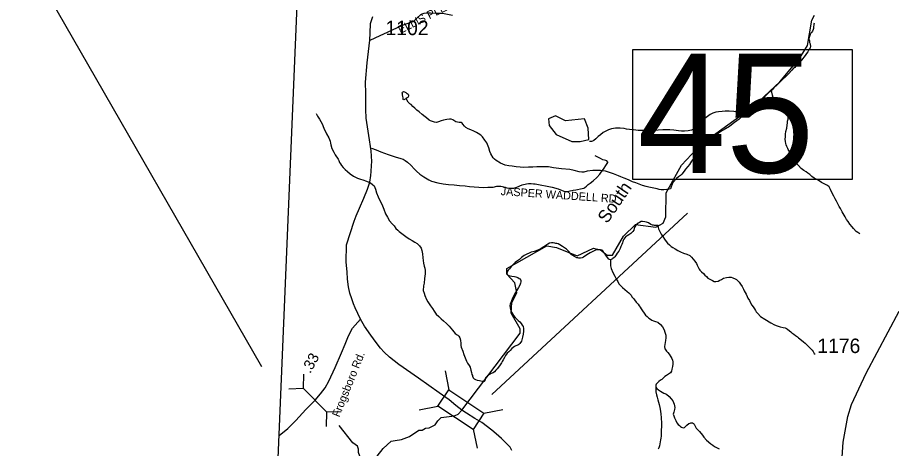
# Model space of a CAD drawing. Extents: x 1950930 to 2061844, y 904556 to 1017002.
# Drawn here: x 1953252 to 1963523, y 946514 to 951576 of the extents above; entities that cross this region are included whole.
import ezdxf

# ---------------------------------------------------------------- set-up
doc = ezdxf.new("R2010")
doc.units = 0
for name, color, linetype in [('Exist Boundary Political CountyLine', 7, 'Continuous'), ('Exist Hydrographic Creek Single Shore', 7, 'Continuous'), ('Exist Hydrographic Creek Single Shore Label', 7, 'Continuous'), ('Exist Hydrographic Misc Water Feature', 7, 'Continuous'), ('Exist Road Non-System Type 51', 7, 'Continuous'), ('Exist Road Non-System Type 51 Label', 7, 'Continuous'), ('Exist Road Primary Interstate Structure Ovrhead Sign Attributed CELL', 7, 'Continuous'), ('Exist Road Primary US Structure Standard Bridge CELL', 7, 'Continuous'), ('Exist Road Secondary Structure Pipe Number Label', 7, 'Continuous'), ('Exist Road Secondary Structure Standard Bridge CELL', 7, 'Continuous'), ('Exist Road Secondary Structure Standard Bridge Number Label', 7, 'Continuous'), ('Exist Road Secondary Type 41 Attributed', 7, 'Continuous'), ('Exist Road Secondary Type 51 Attributed', 7, 'Continuous'), ('Exist Road Secondary Type 51 Label', 7, 'Continuous'), ('Exist Road Secondary Type 51 Number Label', 7, 'Continuous')]:
    doc.layers.add(name, color=color, linetype=linetype)

msp = doc.modelspace()

# ---------------------------------------------------------------- linework, layer by layer
at = {"layer": 'Exist Boundary Political CountyLine'}
msp.add_lwpolyline([(1954667, 907078), (1956980, 962279), (1958720, 998184), (1959482, 1016167)], dxfattribs=at)
at = {"layer": 'Exist Hydrographic Creek Single Shore'}
for points in [[(1957969, 946730), (1958006, 946730), (1958048, 946752), (1958090, 946758), (1958159, 946790), (1958193, 946839), (1958230, 946879), (1958357, 946895), (1958397, 946900), (1958431, 946919), (1958473, 946966), (1959161, 947868), (1959161, 947920), (1959053, 948103), (1959062, 948227), (1959120, 948344), (1959095, 948460), (1959004, 948560), (1959004, 948629), (1959471, 948895), (1959588, 948876), (1959829, 948776), (1960021, 948867), (1960105, 948849), (1960180, 948785), (1960246, 948784), (1960372, 949008), (1960514, 949143), (1960755, 949115), (1960839, 949159), (1960872, 949234), (1960873, 949516), (1961057, 949840), (1961291, 950092), (1961908, 950538), (1962209, 950821), (1962451, 951105), (1962535, 951247), (1962585, 951545), (1962619, 951604)], [(1960779, 949133), (1960777, 949129), (1960781, 949111), (1960785, 949093), (1960795, 949071), (1960817, 949033), (1960835, 949005), (1960855, 948973), (1960875, 948943), (1960889, 948927), (1960915, 948905), (1960935, 948887), (1960953, 948873), (1960979, 948859), (1961013, 948841), (1961045, 948825), (1961079, 948809), (1961119, 948795), (1961152, 948779), (1961174, 948759), (1961194, 948737), (1961212, 948715), (1961230, 948688), (1961238, 948666), (1961250, 948642), (1961262, 948620), (1961272, 948610), (1961290, 948590), (1961314, 948570), (1961330, 948548), (1961348, 948534), (1961366, 948514), (1961388, 948504), (1961418, 948486), (1961438, 948476), (1961450, 948474), (1961460, 948474), (1961484, 948480), (1961504, 948490), (1961526, 948500), (1961550, 948514), (1961582, 948524), (1961612, 948528), (1961638, 948526), (1961660, 948518), (1961684, 948506), (1961700, 948498), (1961714, 948486), (1961732, 948467), (1961750, 948443), (1961768, 948415), (1961782, 948385), (1961792, 948365), (1961804, 948345), (1961814, 948325), (1961828, 948299), (1961836, 948281), (1961853, 948253), (1961863, 948233), (1961883, 948197), (1961897, 948177), (1961911, 948155), (1961925, 948133), (1961933, 948119), (1961951, 948099), (1961985, 948065), (1962033, 948031), (1962103, 947989), (1962149, 947967), (1962179, 947953), (1962213, 947942), (1962249, 947936), (1962275, 947930), (1962289, 947924), (1962301, 947914), (1962325, 947896), (1962339, 947884), (1962353, 947872), (1962375, 947856), (1962395, 947842), (1962417, 947826), (1962431, 947814), (1962445, 947800), (1962487, 947768), (1962507, 947750), (1962531, 947728), (1962552, 947708), (1962571, 947690), (1962589, 947670), (1962602, 947652), (1962616, 947630), (1962626, 947622)], [(1960220, 948730), (1960220, 948724), (1960220, 948702), (1960222, 948660), (1960228, 948626), (1960250, 948580), (1960270, 948538), (1960292, 948500), (1960306, 948474), (1960320, 948448), (1960342, 948426), (1960362, 948404), (1960388, 948382), (1960417, 948358), (1960436, 948342), (1960462, 948314), (1960473, 948294), (1960491, 948276), (1960503, 948258), (1960523, 948234), (1960547, 948208), (1960559, 948190), (1960569, 948174), (1960581, 948154), (1960597, 948130), (1960615, 948104), (1960633, 948081), (1960653, 948064), (1960667, 948049), (1960679, 948039), (1960705, 948023), (1960725, 948015), (1960751, 948005), (1960775, 947997), (1960809, 947971), (1960831, 947941), (1960851, 947909), (1960861, 947881), (1960869, 947845), (1960871, 947813), (1960867, 947783), (1960862, 947759), (1960856, 947711), (1960858, 947685), (1960862, 947681), (1960880, 947657), (1960894, 947641), (1960910, 947621), (1960928, 947591), (1960940, 947571), (1960948, 947553), (1960954, 947531), (1960952, 947503), (1960950, 947477), (1960942, 947445), (1960936, 947423), (1960924, 947401), (1960902, 947385), (1960878, 947371), (1960860, 947359), (1960842, 947343), (1960822, 947325), (1960807, 947315), (1960790, 947301), (1960782, 947293), (1960764, 947277), (1960759, 947269), (1960755, 947259), (1960753, 947245), (1960753, 947233)], [(1960753, 947233), (1960753, 947217), (1960753, 947197), (1960753, 947181), (1960761, 947145), (1960769, 947115), (1960775, 947087), (1960785, 947059), (1960793, 947031), (1960801, 946995), (1960807, 946953), (1960811, 946917), (1960815, 946879), (1960817, 946859), (1960819, 946827), (1960819, 946803), (1960819, 946777), (1960816, 946727), (1960816, 946709), (1960816, 946687), (1960816, 946659), (1960814, 946637), (1960808, 946615), (1960806, 946591), (1960802, 946569), (1960798, 946545), (1960788, 946521), (1960782, 946507)], [(1957255, 946350), (1957267, 946376), (1957285, 946395), (1957274, 946425), (1957258, 946466), (1957260, 946505), (1957249, 946542), (1957193, 946579), (1957033, 946783)], [(1957255, 946350), (1957358, 946345), (1957410, 946360), (1957479, 946425), (1957550, 946513), (1957642, 946600), (1957689, 946607), (1957765, 946621), (1957858, 946655), (1957969, 946730)]]:
    msp.add_lwpolyline(points, dxfattribs=at)
at = {"layer": 'Exist Hydrographic Misc Water Feature'}
for points in [[(1962616, 951510), (1962612, 951498), (1962610, 951488), (1962608, 951466), (1962606, 951446), (1962602, 951434), (1962594, 951416), (1962586, 951402), (1962574, 951390), (1962568, 951378), (1962562, 951366), (1962554, 951342), (1962550, 951326), (1962553, 951312), (1962559, 951300), (1962561, 951284), (1962566, 951268), (1962566, 951256), (1962571, 951248), (1962571, 951236), (1962567, 951218), (1962557, 951202), (1962539, 951172), (1962525, 951154), (1962507, 951128), (1962465, 951076), (1962441, 951048), (1962413, 951019), (1962399, 951005), (1962385, 950989), (1962373, 950979), (1962351, 950957), (1962313, 950915), (1962287, 950887), (1962239, 950843), (1962215, 950821), (1962196, 950801), (1962178, 950785), (1962140, 950749), (1962122, 950727), (1962114, 950721)], [(1957818, 950625), (1957814, 950621), (1957798, 950611), (1957790, 950607), (1957786, 950611), (1957784, 950631), (1957782, 950649), (1957778, 950669), (1957776, 950683), (1957774, 950689), (1957776, 950699), (1957788, 950705), (1957798, 950701), (1957808, 950697), (1957816, 950693), (1957824, 950687), (1957830, 950685), (1957842, 950677), (1957846, 950663), (1957846, 950651), (1957844, 950645), (1957838, 950637), (1957830, 950631), (1957818, 950625)], [(1962114, 950721), (1962104, 950711), (1962082, 950693), (1962062, 950675), (1962024, 950637), (1961978, 950591), (1961924, 950547), (1961880, 950507), (1961848, 950482), (1961818, 950458), (1961794, 950438), (1961788, 950434)], [(1963149, 949035), (1963127, 949049), (1963109, 949061), (1963075, 949097), (1963059, 949119), (1963035, 949147), (1963012, 949181), (1962996, 949205), (1962980, 949233), (1962966, 949253), (1962944, 949293), (1962922, 949331), (1962906, 949357), (1962892, 949389), (1962876, 949419), (1962862, 949447), (1962846, 949477), (1962820, 949522), (1962806, 949554), (1962790, 949586), (1962770, 949604), (1962730, 949624), (1962700, 949638), (1962672, 949656), (1962646, 949672), (1962614, 949688), (1962587, 949710), (1962563, 949730), (1962539, 949748), (1962519, 949762), (1962493, 949780), (1962463, 949802), (1962431, 949836), (1962411, 949856), (1962395, 949876), (1962385, 949892), (1962371, 949914), (1962363, 949930), (1962357, 949944), (1962335, 949981), (1962309, 950025), (1962303, 950039), (1962293, 950061), (1962287, 950081), (1962281, 950097), (1962277, 950119), (1962275, 950145), (1962277, 950175), (1962279, 950189), (1962279, 950207), (1962283, 950235), (1962291, 950275), (1962298, 950311), (1962300, 950337), (1962302, 950359), (1962308, 950381), (1962310, 950403), (1962312, 950429), (1962308, 950445), (1962304, 950459), (1962300, 950469), (1962288, 950487), (1962268, 950501), (1962238, 950515), (1962220, 950525), (1962194, 950543), (1962176, 950559), (1962164, 950573), (1962156, 950587), (1962144, 950607), (1962138, 950621), (1962126, 950663), (1962118, 950697), (1962114, 950721)], [(1960924, 949565), (1960912, 949561), (1960884, 949555), (1960846, 949551), (1960816, 949553), (1960792, 949555), (1960768, 949562), (1960728, 949570), (1960670, 949582), (1960638, 949590), (1960598, 949604), (1960558, 949618), (1960520, 949632), (1960480, 949646), (1960434, 949668), (1960382, 949688), (1960342, 949706), (1960314, 949716), (1960254, 949739), (1960198, 949761), (1960162, 949771), (1960130, 949775), (1960104, 949777), (1960066, 949777), (1960014, 949777), (1959948, 949771), (1959906, 949761), (1959882, 949759), (1959854, 949763), (1959792, 949779), (1959742, 949789), (1959644, 949798), (1959550, 949812), (1959492, 949820), (1959426, 949822), (1959354, 949820), (1959308, 949818), (1959256, 949816), (1959200, 949815), (1959160, 949817), (1959114, 949823), (1959064, 949829), (1959024, 949835), (1958982, 949843), (1958954, 949853), (1958928, 949865), (1958878, 949897), (1958856, 949913), (1958840, 949929), (1958816, 949973), (1958802, 950001), (1958789, 950045), (1958767, 950103), (1958745, 950135), (1958717, 950176), (1958697, 950194), (1958665, 950214), (1958645, 950224), (1958615, 950240), (1958581, 950256), (1958549, 950268), (1958519, 950284), (1958503, 950298), (1958485, 950324), (1958479, 950334), (1958465, 950342), (1958443, 950344), (1958421, 950346), (1958403, 950350), (1958367, 950372), (1958349, 950380), (1958327, 950382), (1958299, 950378), (1958257, 950369), (1958229, 950361), (1958199, 950349), (1958175, 950343), (1958151, 950345), (1958129, 950353), (1958107, 950363), (1958091, 950369), (1958057, 950397), (1958041, 950411), (1958009, 950437), (1957973, 950467), (1957943, 950489), (1957923, 950509), (1957899, 950531), (1957877, 950553), (1957864, 950563), (1957844, 950583), (1957826, 950609), (1957818, 950625)], [(1956763, 950449), (1956779, 950417), (1956801, 950383), (1956831, 950327), (1956853, 950275), (1956885, 950209), (1956911, 950161), (1956925, 950125), (1956931, 950099), (1956934, 950081), (1956944, 950039), (1956968, 949995), (1956986, 949963), (1957020, 949911), (1957030, 949895), (1957036, 949873), (1957048, 949857), (1957060, 949839), (1957080, 949813), (1957104, 949789), (1957128, 949769), (1957162, 949739), (1957200, 949712), (1957248, 949690), (1957284, 949678), (1957312, 949670), (1957352, 949652), (1957382, 949642), (1957400, 949634), (1957424, 949616), (1957444, 949598), (1957460, 949560), (1957469, 949518), (1957491, 949468), (1957511, 949428), (1957533, 949384), (1957555, 949324), (1957577, 949270), (1957599, 949230), (1957625, 949189), (1957653, 949153), (1957677, 949127), (1957699, 949099), (1957721, 949077), (1957737, 949061), (1957767, 949037), (1957817, 949003), (1957856, 948977), (1957890, 948957), (1957920, 948939), (1957950, 948923), (1957978, 948895), (1957994, 948867), (1958002, 948839), (1958012, 948801), (1958016, 948753), (1958024, 948691), (1958032, 948657), (1958040, 948633), (1958044, 948605), (1958044, 948567), (1958040, 948539), (1958036, 948509), (1958031, 948457), (1958025, 948423), (1958021, 948371), (1958029, 948339), (1958039, 948311), (1958057, 948263), (1958073, 948236), (1958107, 948188), (1958127, 948160), (1958147, 948126), (1958173, 948090), (1958203, 948064), (1958231, 948038), (1958259, 948014), (1958295, 947982), (1958324, 947952), (1958346, 947926), (1958364, 947902), (1958396, 947866), (1958418, 947850), (1958428, 947844), (1958440, 947834), (1958452, 947814), (1958456, 947786), (1958460, 947748), (1958462, 947724), (1958466, 947704), (1958484, 947656), (1958496, 947616), (1958512, 947580), (1958530, 947541), (1958542, 947517), (1958558, 947487), (1958570, 947470), (1958580, 947435), (1958589, 947407), (1958593, 947383)], [(1961788, 950434), (1961756, 950448), (1961708, 950464), (1961672, 950470), (1961614, 950476), (1961568, 950474), (1961532, 950472), (1961490, 950466), (1961458, 950462), (1961424, 950452), (1961392, 950436), (1961362, 950414), (1961308, 950373), (1961280, 950345), (1961258, 950319), (1961233, 950295), (1961205, 950269), (1961173, 950253), (1961133, 950245), (1961091, 950239), (1961055, 950241), (1961021, 950245), (1960993, 950247), (1960965, 950251), (1960919, 950255), (1960871, 950257), (1960837, 950255), (1960779, 950252), (1960717, 950250), (1960683, 950250), (1960643, 950250), (1960607, 950250), (1960581, 950250), (1960547, 950250), (1960491, 950256), (1960445, 950262), (1960409, 950266), (1960381, 950272), (1960335, 950276), (1960281, 950275), (1960233, 950267), (1960199, 950255), (1960157, 950237), (1960135, 950225), (1960103, 950199), (1960077, 950177), (1960049, 950151), (1960025, 950133), (1960011, 950125), (1959997, 950121), (1959975, 950121)], [(1961788, 950434), (1961764, 950412), (1961732, 950382), (1961678, 950342), (1961643, 950314), (1961618, 950296), (1961573, 950268), (1961537, 950248), (1961491, 950218), (1961465, 950198), (1961429, 950168), (1961411, 950154), (1961385, 950130), (1961363, 950108), (1961351, 950092), (1961333, 950070), (1961313, 950050), (1961285, 950026), (1961261, 950001), (1961215, 949943), (1961187, 949909), (1961173, 949887), (1961148, 949851), (1961130, 949825), (1961104, 949793), (1961088, 949771), (1961060, 949737), (1961042, 949719), (1961018, 949703), (1960996, 949685), (1960958, 949641), (1960944, 949617), (1960932, 949587), (1960924, 949565)], [(1959865, 950118), (1959966, 950142), (1959957, 950277), (1959916, 950386), (1959691, 950361), (1959574, 950419), (1959491, 950385), (1959499, 950309), (1959582, 950202), (1959765, 950120), (1959865, 950118)], [(1960779, 949133), (1960761, 949131), (1960739, 949131), (1960725, 949136), (1960715, 949137), (1960695, 949145), (1960667, 949164), (1960643, 949172), (1960625, 949176), (1960597, 949180), (1960581, 949178), (1960561, 949170), (1960545, 949160), (1960519, 949138), (1960505, 949118), (1960499, 949098), (1960493, 949078), (1960483, 949064), (1960473, 949050), (1960461, 949040), (1960449, 949030), (1960437, 949022), (1960417, 949012), (1960401, 949002), (1960389, 948988), (1960379, 948974), (1960371, 948958), (1960367, 948944), (1960363, 948928), (1960355, 948908), (1960344, 948888), (1960335, 948862), (1960319, 948832), (1960300, 948808), (1960286, 948788), (1960272, 948766), (1960264, 948758), (1960250, 948746), (1960246, 948742), (1960230, 948732), (1960226, 948730), (1960220, 948730)], [(1960220, 948730), (1960210, 948732), (1960206, 948734), (1960198, 948742), (1960188, 948755), (1960172, 948773), (1960158, 948795), (1960148, 948807), (1960140, 948823), (1960132, 948835), (1960121, 948843), (1960105, 948847), (1960099, 948847), (1960075, 948849), (1960051, 948847), (1960020, 948831), (1959982, 948813), (1959944, 948789), (1959904, 948761), (1959888, 948753), (1959868, 948751), (1959850, 948751), (1959836, 948753), (1959824, 948755), (1959798, 948767), (1959760, 948793), (1959744, 948809), (1959738, 948821), (1959724, 948837), (1959702, 948853), (1959681, 948872), (1959657, 948888), (1959627, 948906), (1959606, 948916), (1959590, 948922), (1959580, 948922), (1959566, 948926), (1959547, 948928), (1959527, 948930), (1959505, 948926), (1959484, 948914), (1959471, 948904), (1959438, 948884), (1959396, 948856), (1959346, 948834), (1959322, 948826), (1959288, 948818), (1959264, 948808), (1959238, 948796), (1959206, 948780), (1959176, 948756), (1959152, 948734), (1959128, 948717), (1959102, 948699), (1959074, 948671), (1959058, 948655), (1959032, 948623), (1959020, 948609), (1959010, 948597), (1959006, 948583), (1959004, 948573), (1959014, 948551), (1959024, 948545), (1959042, 948541), (1959062, 948539), (1959092, 948533), (1959110, 948529), (1959132, 948523), (1959148, 948512), (1959158, 948506), (1959166, 948488), (1959166, 948470), (1959164, 948456), (1959154, 948434), (1959138, 948405), (1959117, 948367), (1959097, 948335), (1959079, 948303), (1959069, 948279), (1959057, 948249), (1959049, 948225), (1959043, 948211), (1959037, 948189), (1959041, 948165), (1959049, 948137), (1959059, 948115), (1959069, 948097), (1959081, 948077), (1959101, 948051), (1959117, 948035), (1959137, 948018), (1959155, 948000), (1959171, 947980), (1959183, 947964), (1959193, 947946), (1959198, 947922), (1959198, 947890), (1959196, 947858), (1959188, 947822), (1959174, 947774)], [(1959174, 947774), (1959156, 947748), (1959144, 947736), (1959130, 947728), (1959108, 947720), (1959092, 947712), (1959078, 947700), (1959062, 947688), (1959042, 947663), (1959026, 947649), (1959008, 947633), (1958988, 947605), (1958976, 947581), (1958960, 947557), (1958948, 947535), (1958938, 947519), (1958926, 947495), (1958904, 947471), (1958890, 947451), (1958875, 947435), (1958859, 947415), (1958841, 947401), (1958817, 947393), (1958806, 947387), (1958792, 947379), (1958785, 947377), (1958775, 947369), (1958763, 947357), (1958753, 947343), (1958747, 947323), (1958743, 947307), (1958741, 947303)], [(1958593, 947383), (1958597, 947373), (1958599, 947363), (1958605, 947345), (1958617, 947333), (1958633, 947325), (1958655, 947317), (1958683, 947311), (1958711, 947305), (1958741, 947303)], [(1960753, 947233), (1960767, 947217), (1960783, 947201), (1960807, 947187), (1960847, 947165), (1960877, 947151), (1960911, 947123), (1960935, 947099), (1960953, 947075), (1960969, 947033), (1960975, 946995), (1960971, 946971), (1960963, 946939), (1960959, 946919), (1960963, 946899), (1960971, 946875), (1960979, 946857), (1960987, 946841), (1961001, 946815), (1961015, 946797), (1961033, 946783), (1961045, 946773), (1961055, 946765), (1961073, 946758), (1961089, 946762), (1961100, 946768), (1961119, 946788), (1961141, 946806), (1961155, 946812), (1961165, 946816), (1961185, 946814), (1961195, 946806), (1961203, 946798), (1961214, 946776), (1961228, 946754), (1961249, 946728), (1961266, 946712), (1961300, 946670), (1961318, 946646), (1961350, 946612), (1961400, 946570), (1961424, 946552), (1961444, 946538), (1961466, 946526), (1961496, 946510)]]:
    msp.add_lwpolyline(points, dxfattribs=at)
at = {"layer": 'Exist Road Non-System Type 51'}
for points in [[(1957397, 951310), (1957512, 951363), (1957600, 951404), (1957719, 951459), (1957789, 951488), (1957854, 951512), (1957881, 951521), (1957896, 951528), (1957914, 951538), (1957929, 951551), (1957944, 951566), (1957992, 951609), (1958008, 951618), (1958029, 951628), (1958057, 951631), (1958106, 951629), (1958183, 951626), (1958229, 951625), (1958264, 951623), (1958326, 951612), (1958365, 951602)], [(1957412, 950043), (1957468, 950020), (1957521, 949999), (1957606, 949968), (1957690, 949939), (1957758, 949918), (1957783, 949910), (1957809, 949898), (1957837, 949875), (1957873, 949842), (1957916, 949796), (1957939, 949770), (1957979, 949737), (1958027, 949705), (1958086, 949668), (1958116, 949654), (1958190, 949634), (1958256, 949622), (1958318, 949615), (1958383, 949609), (1958447, 949604), (1958514, 949598), (1958562, 949592), (1958728, 949581), (1958780, 949582), (1958841, 949585), (1958884, 949594), (1958913, 949596), (1958930, 949595), (1958953, 949591), (1958984, 949582), (1959004, 949575), (1959025, 949573), (1959083, 949572), (1959120, 949584), (1959181, 949609), (1959234, 949622), (1959258, 949625), (1959288, 949625), (1959314, 949624), (1959336, 949624), (1959536, 949583), (1959606, 949564), (1959672, 949537), (1959697, 949534), (1959721, 949534), (1959745, 949539), (1959783, 949547), (1959813, 949553), (1959886, 949568), (1959907, 949571), (1959920, 949580), (1959938, 949593), (1959959, 949613), (1959981, 949629), (1960016, 949658), (1960062, 949698), (1960094, 949737), (1960110, 949758), (1960137, 949793), (1960172, 949849), (1960188, 949871), (1960190, 949878), (1960179, 949891), (1960164, 949895), (1960152, 949900), (1960132, 949905), (1960104, 949921), (1960049, 949948), (1960041, 949953)]]:
    msp.add_lwpolyline(points, dxfattribs=at)
at = {"layer": 'Exist Road Primary Interstate Structure Ovrhead Sign Attributed CELL'}
for p, q in [((1956612, 947387), (1956608, 947221)), ((1956441, 947216), (1956608, 947221)), ((1956889, 946941), (1956608, 947221)), ((1956885, 946774), (1956889, 946941)), ((1957055, 946946), (1956889, 946941))]:
    msp.add_line(p, q, dxfattribs=at)
at = {"layer": 'Exist Road Secondary Structure Pipe Number Label'}
msp.add_line((1956123, 947472), (1953252, 952468), dxfattribs=at)
at = {"layer": 'Exist Road Secondary Structure Standard Bridge CELL'}
for p, q in [((1958277, 947426), (1958322, 947204)), ((1957971, 946967), (1958193, 947011)), ((1958734, 946928), (1958956, 946972)), ((1958608, 946740), (1958652, 946518))]:
    msp.add_line(p, q, dxfattribs=at)
msp.add_lwpolyline([(1958322, 947204), (1958734, 946929), (1958606, 946736), (1958193, 947011)], close=True, dxfattribs=at)
at = {"layer": 'Exist Road Secondary Structure Standard Bridge Number Label'}
msp.add_line((1958826, 947149), (1961126, 949278), dxfattribs=at)
msp.add_lwpolyline([(1960484, 951201), (1963061, 951201), (1963061, 949672), (1960484, 949672)], close=True, dxfattribs=at)
at = {"layer": 'Exist Road Secondary Type 41 Attributed'}
msp.add_lwpolyline([(1956326, 946667), (1956427, 946748), (1956524, 946843), (1956639, 946970), (1956748, 947081), (1956812, 947155), (1956866, 947227), (1956909, 947304), (1956986, 947464), (1957061, 947639), (1957104, 947739), (1957141, 947837), (1957188, 947927), (1957283, 948032)], dxfattribs=at)
at = {"layer": 'Exist Road Secondary Type 51 Attributed'}
for points in [[(1957283, 948032), (1957220, 948166), (1957201, 948214), (1957180, 948272), (1957159, 948338), (1957142, 948414), (1957128, 948502), (1957125, 948588), (1957116, 948704), (1957119, 948907), (1957210, 949182), (1957233, 949245), (1957270, 949337), (1957323, 949455), (1957365, 949558), (1957391, 949640), (1957406, 949722), (1957408, 949768), (1957411, 949838), (1957416, 949884), (1957407, 950011), (1957382, 950188), (1957351, 950392), (1957345, 950494), (1957344, 950574), (1957344, 950684), (1957341, 950815), (1957362, 951044), (1957392, 951310), (1957398, 951393), (1957401, 951506), (1957429, 951589)], [(1962940, 946353), (1962956, 946587), (1963009, 946888), (1963053, 947032), (1963225, 947400), (1963613, 948126)], [(1958473, 946966), (1958403, 947017), (1958326, 947086), (1958208, 947167), (1957963, 947340), (1957734, 947499), (1957625, 947586), (1957561, 947646), (1957519, 947692), (1957468, 947759), (1957406, 947843), (1957331, 947951), (1957283, 948032)], [(1959060, 946492), (1959042, 946528), (1958941, 946632), (1958877, 946685), (1958826, 946729), (1958710, 946820), (1958627, 946868), (1958527, 946930), (1958473, 946966)]]:
    msp.add_lwpolyline(points, dxfattribs=at)

# ---------------------------------------------------------------- texts
at = {"layer": 'Exist Hydrographic Creek Single Shore Label'}
msp.add_text('South', height=150, rotation=55.6335, dxfattribs=at).set_placement((1960182, 949147))
at = {"layer": 'Exist Road Non-System Type 51 Label'}
for s, rotation, p in [('  ELLIS PLEASANT DR', 26.7374, (1957689, 951351)), ('  JASPER WADDELL RD', 356.177, (1958858, 949495))]:
    msp.add_text(s, height=95, rotation=rotation, dxfattribs=at).set_placement(p)
at = {"layer": 'Exist Road Primary US Structure Standard Bridge CELL'}
msp.add_text('.33', height=125, rotation=61.2972, dxfattribs=at).set_placement((1956692, 947387))
at = {"layer": 'Exist Road Secondary Structure Standard Bridge Number Label'}
msp.add_text('45', height=1400, dxfattribs=at).set_placement((1960535, 949751))
at = {"layer": 'Exist Road Secondary Type 51 Label'}
msp.add_text('Frogsboro Rd.', height=95, rotation=68.0657, dxfattribs=at).set_placement((1957033, 946875))
at = {"layer": 'Exist Road Secondary Type 51 Number Label'}
for s, p in [('1102', (1957577, 951369)), ('1176', (1962651, 947635))]:
    msp.add_text(s, height=170, dxfattribs=at).set_placement(p)

doc.saveas('drawing.dxf')
